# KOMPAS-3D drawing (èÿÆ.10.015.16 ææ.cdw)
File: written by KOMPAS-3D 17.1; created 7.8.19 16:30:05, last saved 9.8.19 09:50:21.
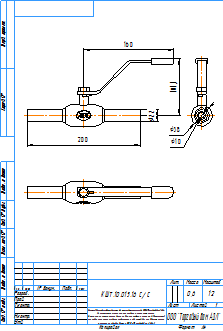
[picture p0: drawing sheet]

Sheet 1: A4, portrait

Title block, sheet 1: name: КШТ.10.015.16 С/С; material: Сталь 20  ГОСТ 1050-2013; mass: 0,6; sheets: 1; sheet format: A4; stored path: C:\Users\kka\KOMPAS_Work\Модели кранов для исследований\DN65\КШТ.10.065.16 СС.cdw

Views: Вид 1, Проекционный вид 2, Проекционный вид 3
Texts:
  kka
  adl
  Рама для чертежей
  Лит-Масса-Масштаб
  Материал-Предприятие
  Масштаб
  Изм.
  Лист
  № докум.
  Подп.
  Дата
  Лит.
  Разраб.
  Пров.
  Т.контр.
  Листов
  Внимание! Данный продукт является объектом авторского права ООО «Торговый Дом АДЛ».
  Запрещается изменение, копирование, распространение
  (в том числе путем копирования на другие сайты и ресурсы в Интернете)
  или любое иное использование информации и объектов без предварительного
  согласия правообладателя (ООО «Торговый Дом АДЛ»).
  Н.контр.
  Утв.
  ООО "Торговый дом АДЛ"
  Изменение
  Номер документа
  Подпись
  Обозначение документа
  Наименование изделия
  Масса изделия по ГОСТ 2.109-73
  Порядковый номер листа
  Общее количество листов в документе
  Характер работы, выполненной лицом, подписавшим документ
  Наименование или индекс предприятия, выпускающего документ
  Инв. № подл.
  Подп. и дата
  Взам. инв. №
  Инв. № дубл.
  Инвентарный номер подлинника по ГОСТ 2.501-68
  Подпись принявшего подлинник в отдел технической документации
  Инвентарный номер подлинника, взамен которого выпущен данный подлинник
  Инвентарный номер дубликата по ГОСТ 2.502-68
  Подпись принявшего дубликат в отдел технической документации
  Справ. №
  Перв. примен.
  Обозначение документа, взамен или на основании которого выпущен данный документ
  Обозначение документа, в котором впервые записан данный документ
  Подпись лица, копировавшего чертеж
  Обозначение формата листа
  !Рама для чертежа
Dimensions and other numbers on the sheet: 160; 101,1; 22; 200; 38; 10; 1:2; 1; 0,6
